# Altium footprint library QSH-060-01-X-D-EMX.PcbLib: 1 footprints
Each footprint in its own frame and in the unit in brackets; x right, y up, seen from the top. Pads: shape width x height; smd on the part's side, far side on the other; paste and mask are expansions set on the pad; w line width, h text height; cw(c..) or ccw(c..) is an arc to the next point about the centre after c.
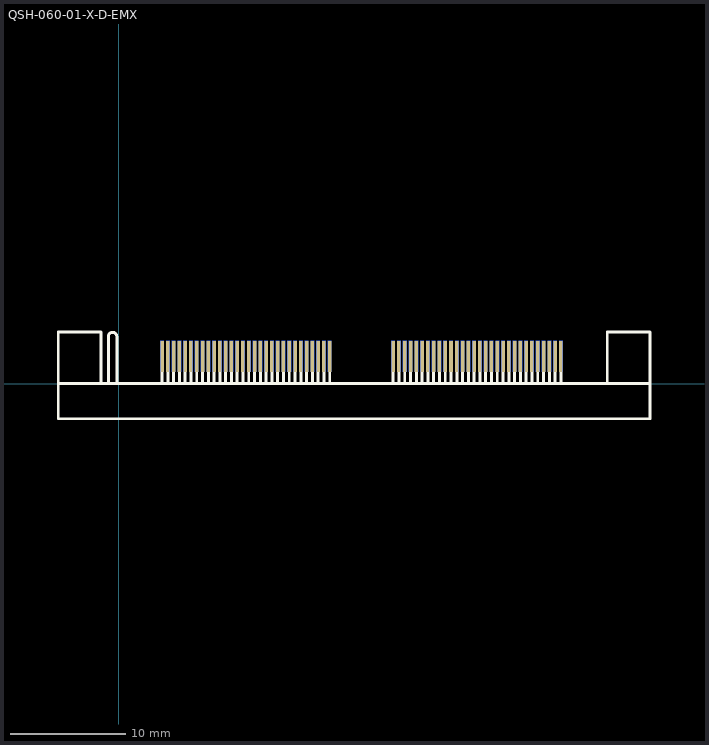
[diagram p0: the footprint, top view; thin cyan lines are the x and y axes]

## QSH-060-01-X-D-EMX [mil] "0.50mm pitch, 120 pin, connector; w/edge mounts"
height 142.52
pads (120):
  rect 12x105 smd far side mask+0: 1(147,92.5) 3(166.7,92.5) 5(186.4,92.5) 7(206.1,92.5) 9(225.8,92.5) 11(245.5,92.5) 13(265.2,92.5) 15(284.9,92.5) 17(304.6,92.5) 19(324.3,92.5) 21(344,92.5) 23(363.7,92.5) 25(383.4,92.5) 27(403.1,92.5) 29(422.8,92.5) 31(442.5,92.5) 33(462.2,92.5) 35(481.9,92.5) 37(501.6,92.5) 39(521.3,92.5) 41(541,92.5) 43(560.7,92.5) 45(580.4,92.5) 47(600.1,92.5) 49(619.8,92.5) 51(639.5,92.5) 53(659.2,92.5) 55(678.9,92.5) 57(698.6,92.5) 59(718.3,92.5) 61(934.5,92.5) 63(954.2,92.5) 65(973.9,92.5) 67(993.6,92.5) 69(1013.3,92.5) 71(1033,92.5) 73(1052.7,92.5) 75(1072.4,92.5) 77(1092.1,92.5) 79(1111.8,92.5) 81(1131.5,92.5) 83(1151.2,92.5) 85(1170.9,92.5) 87(1190.6,92.5) 89(1210.3,92.5) 91(1230,92.5) 93(1249.7,92.5) 95(1269.4,92.5) 97(1289.1,92.5) 99(1308.8,92.5) 101(1328.5,92.5) 103(1348.2,92.5) 105(1367.9,92.5) 107(1387.6,92.5) 109(1407.3,92.5) 111(1427,92.5) 113(1446.7,92.5) 115(1466.4,92.5) 117(1486.1,92.5) 119(1505.8,92.5)
  rect 12x105 smd mask+0: 2(147,92.5) 4(166.7,92.5) 6(186.4,92.5) 8(206.1,92.5) 10(225.8,92.5) 12(245.5,92.5) 14(265.2,92.5) 16(284.9,92.5) 18(304.6,92.5) 20(324.3,92.5) 22(344,92.5) 24(363.7,92.5) 26(383.4,92.5) 28(403.1,92.5) 30(422.8,92.5) 32(442.5,92.5) 34(462.2,92.5) 36(481.9,92.5) 38(501.6,92.5) 40(521.3,92.5) 42(541,92.5) 44(560.7,92.5) 46(580.4,92.5) 48(600.1,92.5) 50(619.8,92.5) 52(639.5,92.5) 54(659.2,92.5) 56(678.9,92.5) 58(698.6,92.5) 60(718.3,92.5) 62(934.5,92.5) 64(954.2,92.5) 66(973.9,92.5) 68(993.6,92.5) 70(1013.3,92.5) 72(1033,92.5) 74(1052.7,92.5) 76(1072.4,92.5) 78(1092.1,92.5) 80(1111.8,92.5) 82(1131.5,92.5) 84(1151.2,92.5) 86(1170.9,92.5) 88(1190.6,92.5) 90(1210.3,92.5) 92(1230,92.5) 94(1249.7,92.5) 96(1269.4,92.5) 98(1289.1,92.5) 100(1308.8,92.5) 102(1328.5,92.5) 104(1348.2,92.5) 106(1367.9,92.5) 108(1387.6,92.5) 110(1407.3,92.5) 112(1427,92.5) 114(1446.7,92.5) 116(1466.4,92.5) 118(1486.1,92.5) 120(1505.8,92.5)
Top Overlay:
  lines w10: -206.65,0 -62,0 ; -36,0 -36,160 cw(c-21.5,160) -7.01,160 -7,0 ; 147,0 147,110 ; 166.7,0 166.7,110 ; 186.4,0 186.4,110 ; 206.1,0 206.1,110 ; 225.8,0 225.8,110 ; 245.5,0 245.5,110 ; 265.2,0 265.2,110 ; 284.9,0 284.9,110 ; 304.6,0 304.6,110 ; 324.3,0 324.3,110 ; 344,0 344,110 ; 363.7,0 363.7,110 ; 383.4,0 383.4,110 ; 403.1,0 403.1,110 ; 422.8,0 422.8,110 ; 442.5,0 442.5,110 ; 462.2,0 462.2,110 ; 481.9,0 481.9,110 ; 501.6,0 501.6,110 ; 521.3,0 521.3,110 ; 541,0 541,110 ; 560.7,0 560.7,110 ; 580.4,0 580.4,110 ; 600.1,0 600.1,110 ; 619.8,0 619.8,110 ; 639.5,0 639.5,110 ; 659.2,0 659.2,110 ; 678.9,0 678.9,110 ; 698.6,0 698.6,110 ; 718.3,0 718.3,110 ; 934.5,0 934.5,110 ; 954.2,0 954.2,110 ; 973.9,0 973.9,110 ; 993.6,0 993.6,110 ; 1013.3,0 1013.3,110 ; 1033,0 1033,110 ; 1052.7,0 1052.7,110 ; 1072.4,0 1072.4,110 ; 1092.1,0 1092.1,110 ; 1111.8,0 1111.8,110 ; 1131.5,0 1131.5,110 ; 1151.2,0 1151.2,110 ; 1170.9,0 1170.9,110 ; 1190.6,0 1190.6,110 ; 1210.3,0 1210.3,110 ; 1230,0 1230,110 ; 1249.7,0 1249.7,110 ; 1269.4,0 1269.4,110 ; 1289.1,0 1289.1,110 ; 1308.8,0 1308.8,110 ; 1328.5,0 1328.5,110 ; 1348.2,0 1348.2,110 ; 1367.9,0 1367.9,110 ; 1387.6,0 1387.6,110 ; 1407.3,0 1407.3,110 ; 1427,0 1427,110 ; 1446.7,0 1446.7,110 ; 1466.4,0 1466.4,110 ; 1486.1,0 1486.1,110 ; 1505.8,0 1505.8,110 ; 1664.5,0 1808.85,0 ; -206.65,-120 -206.65,175 -61.65,175 -61.65,0 1663.85,0 1663.85,175 1808.85,175 1808.85,-120 -206.65,-120
Top Solder:
  lines w5: 147,99 147,145 ; 166.7,99 166.7,145 ; 186.4,99 186.4,145 ; 206.1,99 206.1,145 ; 225.8,99 225.8,145 ; 245.5,99 245.5,145 ; 265.2,99 265.2,145 ; 284.9,99 284.9,145 ; 304.6,99 304.6,145 ; 324.3,99 324.3,145 ; 344,99 344,145 ; 363.7,99 363.7,145 ; 383.4,99 383.4,145 ; 403.1,99 403.1,145 ; 422.8,99 422.8,145 ; 442.5,99 442.5,145 ; 462.2,99 462.2,145 ; 481.9,99 481.9,145 ; 501.6,99 501.6,145 ; 521.3,99 521.3,145 ; 541,99 541,145 ; 560.7,99 560.7,145 ; 580.4,99 580.4,145 ; 600.1,99 600.1,145 ; 619.8,99 619.8,145 ; 639.5,99 639.5,145 ; 659.2,99 659.2,145 ; 678.9,99 678.9,145 ; 698.6,99 698.6,145 ; 718.3,99 718.3,145 ; 934.5,99 934.5,145 ; 954.2,99 954.2,145 ; 973.9,99 973.9,145 ; 993.6,99 993.6,145 ; 1013.3,99 1013.3,145 ; 1033,99 1033,145 ; 1052.7,99 1052.7,145 ; 1072.4,99 1072.4,145 ; 1092.1,99 1092.1,145 ; 1111.8,99 1111.8,145 ; 1131.5,99 1131.5,145 ; 1151.2,99 1151.2,145 ; 1170.9,99 1170.9,145 ; 1190.6,99 1190.6,145 ; 1210.3,99 1210.3,145 ; 1230,99 1230,145 ; 1249.7,99 1249.7,145 ; 1269.4,99 1269.4,145 ; 1289.1,99 1289.1,145 ; 1308.8,99 1308.8,145 ; 1328.5,99 1328.5,145 ; 1348.2,99 1348.2,145 ; 1367.9,99 1367.9,145 ; 1387.6,99 1387.6,145 ; 1407.3,99 1407.3,145 ; 1427,99 1427,145 ; 1446.7,99 1446.7,145 ; 1466.4,99 1466.4,145 ; 1486.1,99 1486.1,145 ; 1505.8,99 1505.8,145
Bottom Solder:
  lines w5: 147,99 147,145 ; 166.7,99 166.7,145 ; 186.4,99 186.4,145 ; 206.1,99 206.1,145 ; 225.8,99 225.8,145 ; 245.5,99 245.5,145 ; 265.2,99 265.2,145 ; 284.9,99 284.9,145 ; 304.6,99 304.6,145 ; 324.3,99 324.3,145 ; 344,99 344,145 ; 363.7,99 363.7,145 ; 383.4,99 383.4,145 ; 403.1,99 403.1,145 ; 422.8,99 422.8,145 ; 442.5,99 442.5,145 ; 462.2,99 462.2,145 ; 481.9,99 481.9,145 ; 501.6,99 501.6,145 ; 521.3,99 521.3,145 ; 541,99 541,145 ; 560.7,99 560.7,145 ; 580.4,99 580.4,145 ; 600.1,99 600.1,145 ; 619.8,99 619.8,145 ; 639.5,99 639.5,145 ; 659.2,99 659.2,145 ; 678.9,99 678.9,145 ; 698.6,99 698.6,145 ; 718.3,99 718.3,145 ; 934.5,99 934.5,145 ; 954.2,99 954.2,145 ; 973.9,99 973.9,145 ; 993.6,99 993.6,145 ; 1013.3,99 1013.3,145 ; 1033,99 1033,145 ; 1052.7,99 1052.7,145 ; 1072.4,99 1072.4,145 ; 1092.1,99 1092.1,145 ; 1111.8,99 1111.8,145 ; 1131.5,99 1131.5,145 ; 1151.2,99 1151.2,145 ; 1170.9,99 1170.9,145 ; 1190.6,99 1190.6,145 ; 1210.3,99 1210.3,145 ; 1230,99 1230,145 ; 1249.7,99 1249.7,145 ; 1269.4,99 1269.4,145 ; 1289.1,99 1289.1,145 ; 1308.8,99 1308.8,145 ; 1328.5,99 1328.5,145 ; 1348.2,99 1348.2,145 ; 1367.9,99 1367.9,145 ; 1387.6,99 1387.6,145 ; 1407.3,99 1407.3,145 ; 1427,99 1427,145 ; 1446.7,99 1446.7,145 ; 1466.4,99 1466.4,145 ; 1486.1,99 1486.1,145 ; 1505.8,99 1505.8,145
Mechanical 13:
  lines w3.94: -206.65,0 -62,0 ; -36,0 -36,160 cw(c-21.5,160) -7,160 -7,0 ; 147,0 147,110 ; 166.7,0 166.7,110 ; 186.4,0 186.4,110 ; 206.1,0 206.1,110 ; 225.8,0 225.8,110 ; 245.5,0 245.5,110 ; 265.2,0 265.2,110 ; 284.9,0 284.9,110 ; 304.6,0 304.6,110 ; 324.3,0 324.3,110 ; 344,0 344,110 ; 363.7,0 363.7,110 ; 383.4,0 383.4,110 ; 403.1,0 403.1,110 ; 422.8,0 422.8,110 ; 442.5,0 442.5,110 ; 462.2,0 462.2,110 ; 481.9,0 481.9,110 ; 501.6,0 501.6,110 ; 521.3,0 521.3,110 ; 541,0 541,110 ; 560.7,0 560.7,110 ; 580.4,0 580.4,110 ; 600.1,0 600.1,110 ; 619.8,0 619.8,110 ; 639.5,0 639.5,110 ; 659.2,0 659.2,110 ; 678.9,0 678.9,110 ; 698.6,0 698.6,110 ; 718.3,0 718.3,110 ; 934.5,0 934.5,110 ; 954.2,0 954.2,110 ; 973.9,0 973.9,110 ; 993.6,0 993.6,110 ; 1013.3,0 1013.3,110 ; 1033,0 1033,110 ; 1052.7,0 1052.7,110 ; 1072.4,0 1072.4,110 ; 1092.1,0 1092.1,110 ; 1111.8,0 1111.8,110 ; 1131.5,0 1131.5,110 ; 1151.2,0 1151.2,110 ; 1170.9,0 1170.9,110 ; 1190.6,0 1190.6,110 ; 1210.3,0 1210.3,110 ; 1230,0 1230,110 ; 1249.7,0 1249.7,110 ; 1269.4,0 1269.4,110 ; 1289.1,0 1289.1,110 ; 1308.8,0 1308.8,110 ; 1328.5,0 1328.5,110 ; 1348.2,0 1348.2,110 ; 1367.9,0 1367.9,110 ; 1387.6,0 1387.6,110 ; 1407.3,0 1407.3,110 ; 1427,0 1427,110 ; 1446.7,0 1446.7,110 ; 1466.4,0 1466.4,110 ; 1486.1,0 1486.1,110 ; 1505.8,0 1505.8,110 ; 1664.5,0 1808.85,0 ; -206.65,-120 1808.85,-120 1808.85,175 1663.85,175 1663.85,0 -61.65,0 -61.65,175 -206.65,175 -206.65,-120
  text ".Designator" at 0,0 h60
Drill Drawing:
  lines w0.39: -283,0 -43,0 -43,163.5 cw(c-21.5,163.5) 0,163.5 0,0 1885,0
